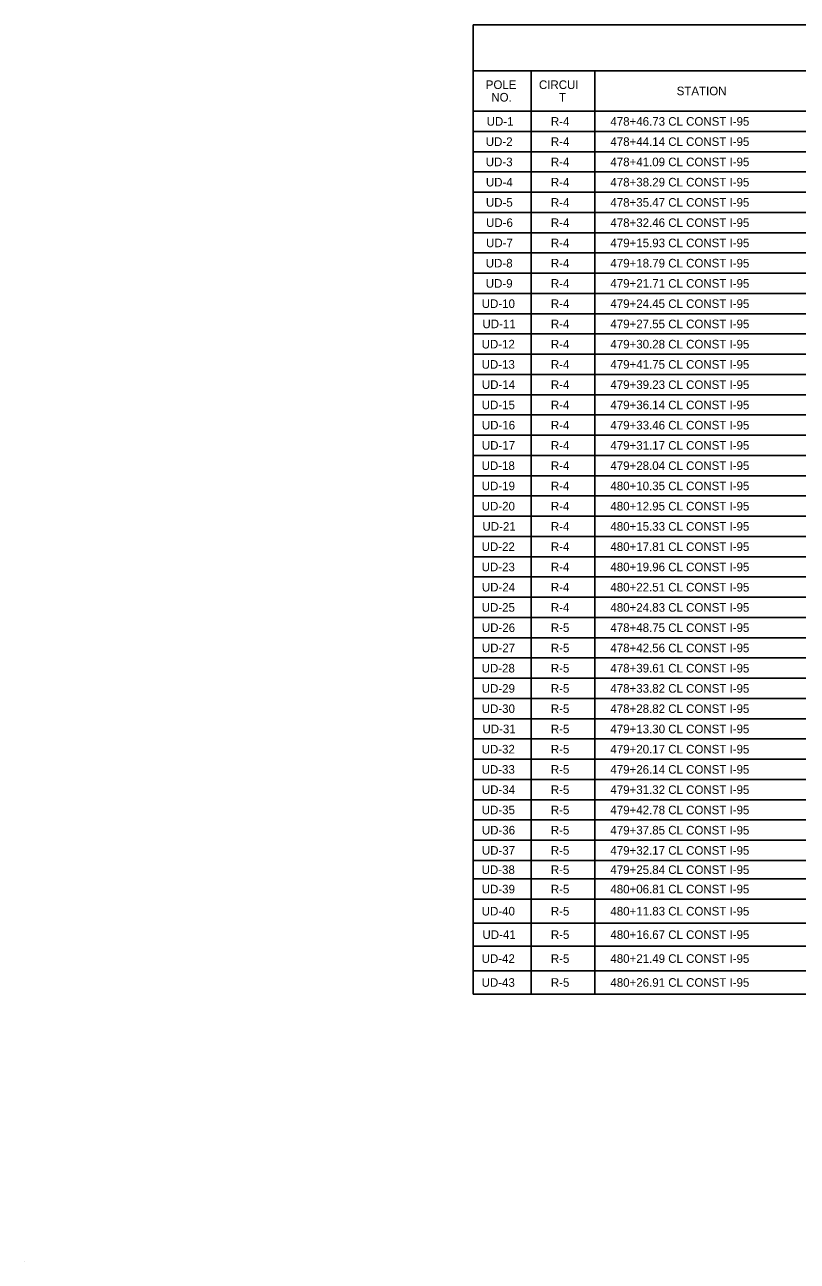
# Model space of a CAD drawing. Extents: x -816.7 to -800.9, y -2209.6 to -2187.8.
# Drawn here: x -816.67 to -810.38, y -2197.9 to -2187.82 of the extents above; entities that cross this region are included whole.
import ezdxf

# ---------------------------------------------------------------- set-up
doc = ezdxf.new("R2010")
doc.units = 0
for name, color, linetype in [('PlotBorder_dp', 7, 'Continuous'), ('SheetBorder_dp', 7, 'Continuous'), ('SheetLines_dp', 7, 'Continuous'), ('TextMinor', 7, 'Continuous'), ('TextShtNo', 7, 'Continuous')]:
    doc.layers.add(name, color=color, linetype=linetype)

msp = doc.modelspace()

# ---------------------------------------------------------------- linework, layer by layer
at = {"layer": 'PlotBorder_dp'}
for p, q in [((-812.544, -2188.198), (-812.544, -2195.721)), ((-812.544, -2188.198), (-812.544, -2195.721)), ((-812.026, -2188.198), (-812.026, -2195.721)), ((-812.026, -2188.198), (-812.026, -2195.721)), ((-813.016, -2188.528), (-803.889, -2188.528))]:
    msp.add_line(p, q, dxfattribs=at)
at = {"layer": 'SheetLines_dp'}
for p, q in [((-813.016, -2187.823), (-802.996, -2187.823)), ((-813.016, -2187.823), (-813.016, -2195.721)), ((-813.016, -2188.198), (-802.996, -2188.198)), ((-813.016, -2188.198), (-802.996, -2188.198)), ((-813.016, -2193.808), (-813.016, -2195.721)), ((-813.016, -2195.721), (-802.996, -2195.721))]:
    msp.add_line(p, q, dxfattribs=at)
at = {"layer": 'TextMinor'}
for p, q in [((-813.016, -2188.528), (-802.996, -2188.528)), ((-813.016, -2188.693), (-802.996, -2188.693)), ((-813.016, -2188.693), (-802.996, -2188.693)), ((-813.016, -2188.858), (-802.996, -2188.858)), ((-813.016, -2188.858), (-802.996, -2188.858)), ((-813.016, -2189.023), (-802.996, -2189.023)), ((-813.016, -2189.023), (-802.996, -2189.023)), ((-813.016, -2189.188), (-802.996, -2189.188)), ((-813.016, -2189.188), (-802.996, -2189.188)), ((-813.016, -2189.353), (-802.996, -2189.353)), ((-813.016, -2189.353), (-802.996, -2189.353)), ((-813.016, -2189.518), (-812.026, -2189.518)), ((-813.016, -2189.518), (-802.996, -2189.518)), ((-813.016, -2189.683), (-802.996, -2189.683)), ((-813.016, -2189.683), (-802.996, -2189.683)), ((-813.016, -2189.848), (-802.996, -2189.848)), ((-813.016, -2189.848), (-802.996, -2189.848)), ((-813.016, -2190.013), (-802.996, -2190.013)), ((-813.016, -2190.013), (-802.996, -2190.013)), ((-813.016, -2190.178), (-802.996, -2190.178)), ((-813.016, -2190.178), (-802.996, -2190.178)), ((-813.016, -2190.343), (-802.996, -2190.343)), ((-813.016, -2190.343), (-802.996, -2190.343)), ((-813.016, -2190.508), (-802.996, -2190.508)), ((-813.016, -2190.508), (-802.996, -2190.508)), ((-813.016, -2190.673), (-802.996, -2190.673)), ((-813.016, -2190.673), (-802.996, -2190.673)), ((-813.016, -2190.838), (-802.996, -2190.838)), ((-813.016, -2190.838), (-802.996, -2190.838)), ((-813.016, -2191.003), (-802.996, -2191.003)), ((-813.016, -2191.003), (-802.996, -2191.003)), ((-813.016, -2191.168), (-802.996, -2191.168)), ((-813.016, -2191.168), (-802.996, -2191.168)), ((-813.016, -2191.333), (-802.996, -2191.333)), ((-813.016, -2191.333), (-802.996, -2191.333)), ((-813.016, -2191.498), (-802.996, -2191.498)), ((-813.016, -2191.498), (-802.996, -2191.498)), ((-813.016, -2191.663), (-802.996, -2191.663)), ((-813.016, -2191.663), (-802.996, -2191.663)), ((-813.016, -2191.828), (-802.996, -2191.828)), ((-813.016, -2191.828), (-802.996, -2191.828)), ((-813.016, -2191.993), (-802.996, -2191.993)), ((-813.016, -2191.993), (-802.996, -2191.993)), ((-813.016, -2192.158), (-802.996, -2192.158)), ((-813.016, -2192.158), (-802.996, -2192.158)), ((-813.016, -2192.323), (-802.996, -2192.323)), ((-813.016, -2192.323), (-802.996, -2192.323)), ((-813.016, -2192.488), (-802.996, -2192.488)), ((-813.016, -2192.488), (-802.996, -2192.488)), ((-813.016, -2192.653), (-802.996, -2192.653)), ((-813.016, -2192.653), (-802.996, -2192.653)), ((-813.016, -2192.818), (-802.996, -2192.818)), ((-813.016, -2192.818), (-802.996, -2192.818)), ((-813.016, -2192.983), (-802.996, -2192.983)), ((-813.016, -2192.983), (-802.996, -2192.983)), ((-813.016, -2193.148), (-802.996, -2193.148)), ((-813.016, -2193.148), (-802.996, -2193.148)), ((-813.016, -2193.313), (-802.996, -2193.313)), ((-813.016, -2193.313), (-802.996, -2193.313)), ((-813.016, -2193.478), (-802.996, -2193.478)), ((-813.016, -2193.478), (-802.996, -2193.478)), ((-813.016, -2193.643), (-802.996, -2193.643)), ((-813.016, -2193.643), (-802.996, -2193.643)), ((-813.016, -2193.808), (-802.996, -2193.808)), ((-813.016, -2193.808), (-802.996, -2193.808)), ((-813.016, -2193.973), (-802.996, -2193.973)), ((-813.016, -2193.973), (-802.996, -2193.973)), ((-813.016, -2194.138), (-802.996, -2194.138)), ((-813.016, -2194.138), (-802.996, -2194.138)), ((-813.016, -2194.303), (-802.996, -2194.303)), ((-813.016, -2194.303), (-802.996, -2194.303)), ((-813.016, -2194.468), (-802.996, -2194.468)), ((-813.016, -2194.468), (-802.996, -2194.468)), ((-813.016, -2194.633), (-802.996, -2194.633)), ((-813.016, -2194.633), (-802.996, -2194.633)), ((-813.016, -2194.783), (-802.996, -2194.783)), ((-813.016, -2194.783), (-802.996, -2194.783)), ((-813.016, -2194.948), (-802.996, -2194.948)), ((-813.016, -2194.948), (-802.996, -2194.948)), ((-813.016, -2195.143), (-802.996, -2195.143)), ((-813.016, -2195.143), (-802.996, -2195.143)), ((-813.016, -2195.331), (-802.996, -2195.331)), ((-813.016, -2195.331), (-802.996, -2195.331)), ((-813.016, -2195.533), (-802.996, -2195.533)), ((-813.016, -2195.533), (-802.996, -2195.533))]:
    msp.add_line(p, q, dxfattribs=at)
at = {"layer": 'TextShtNo'}
msp.add_line((-816.669, -2197.899), (-816.669, -2197.899), dxfattribs=at)

# ---------------------------------------------------------------- texts
at = {"layer": 'SheetBorder_dp'}
for s, p in [('POLE', (-812.913, -2188.347)), ('CIRCUI', (-812.48, -2188.347)), ('STATION', (-811.358, -2188.398)), ('NO.', (-812.868, -2188.449)), ('T', (-812.317, -2188.449)), ('UD-1', (-812.906, -2188.646)), ('R-4', (-812.383, -2188.646)), ('478+46.73 CL CONST I-95', (-811.898, -2188.646)), ('UD-2', (-812.913, -2188.811)), ('R-4', (-812.383, -2188.811)), ('478+44.14 CL CONST I-95', (-811.898, -2188.811)), ('UD-3', (-812.913, -2188.976)), ('R-4', (-812.383, -2188.976)), ('478+41.09 CL CONST I-95', (-811.898, -2188.976)), ('UD-4', (-812.912, -2189.141)), ('R-4', (-812.383, -2189.141)), ('478+38.29 CL CONST I-95', (-811.898, -2189.141)), ('UD-5', (-812.912, -2189.306)), ('R-4', (-812.383, -2189.306)), ('478+35.47 CL CONST I-95', (-811.898, -2189.306)), ('UD-6', (-812.911, -2189.471)), ('R-4', (-812.383, -2189.471)), ('478+32.46 CL CONST I-95', (-811.898, -2189.471)), ('UD-7', (-812.911, -2189.636)), ('R-4', (-812.383, -2189.636)), ('479+15.93 CL CONST I-95', (-811.898, -2189.636)), ('UD-8', (-812.913, -2189.801)), ('R-4', (-812.383, -2189.801)), ('479+18.79 CL CONST I-95', (-811.898, -2189.801)), ('UD-9', (-812.913, -2189.966)), ('R-4', (-812.383, -2189.966)), ('479+21.71 CL CONST I-95', (-811.898, -2189.966)), ('UD-10', (-812.946, -2190.131)), ('R-4', (-812.383, -2190.131)), ('479+24.45 CL CONST I-95', (-811.898, -2190.131)), ('UD-11', (-812.94, -2190.296)), ('R-4', (-812.383, -2190.296)), ('479+27.55 CL CONST I-95', (-811.898, -2190.296)), ('UD-12', (-812.947, -2190.461)), ('R-4', (-812.383, -2190.461)), ('479+30.28 CL CONST I-95', (-811.898, -2190.461)), ('UD-13', (-812.947, -2190.626)), ('R-4', (-812.383, -2190.626)), ('479+41.75 CL CONST I-95', (-811.898, -2190.626)), ('UD-14', (-812.945, -2190.791)), ('R-4', (-812.383, -2190.791)), ('479+39.23 CL CONST I-95', (-811.898, -2190.791)), ('UD-15', (-812.946, -2190.956)), ('R-4', (-812.383, -2190.956)), ('479+36.14 CL CONST I-95', (-811.898, -2190.956)), ('UD-16', (-812.945, -2191.121)), ('R-4', (-812.383, -2191.121)), ('479+33.46 CL CONST I-95', (-811.898, -2191.121)), ('UD-17', (-812.945, -2191.286)), ('R-4', (-812.383, -2191.286)), ('479+31.17 CL CONST I-95', (-811.898, -2191.286)), ('UD-18', (-812.947, -2191.451)), ('R-4', (-812.383, -2191.451)), ('479+28.04 CL CONST I-95', (-811.898, -2191.451)), ('UD-19', (-812.946, -2191.616)), ('R-4', (-812.383, -2191.616)), ('480+10.35 CL CONST I-95', (-811.898, -2191.616)), ('UD-20', (-812.946, -2191.781)), ('R-4', (-812.383, -2191.781)), ('480+12.95 CL CONST I-95', (-811.898, -2191.781)), ('UD-21', (-812.94, -2191.946)), ('R-4', (-812.383, -2191.946)), ('480+15.33 CL CONST I-95', (-811.898, -2191.946)), ('UD-22', (-812.947, -2192.111)), ('R-4', (-812.383, -2192.111)), ('480+17.81 CL CONST I-95', (-811.898, -2192.111)), ('UD-23', (-812.947, -2192.276)), ('R-4', (-812.383, -2192.276)), ('480+19.96 CL CONST I-95', (-811.898, -2192.276)), ('UD-24', (-812.945, -2192.441)), ('R-4', (-812.383, -2192.441)), ('480+22.51 CL CONST I-95', (-811.898, -2192.441)), ('UD-25', (-812.946, -2192.606)), ('R-4', (-812.383, -2192.606)), ('480+24.83 CL CONST I-95', (-811.898, -2192.606)), ('UD-26', (-812.945, -2192.771)), ('R-5', (-812.383, -2192.771)), ('478+48.75 CL CONST I-95', (-811.898, -2192.771)), ('UD-27', (-812.945, -2192.936)), ('R-5', (-812.383, -2192.936)), ('478+42.56 CL CONST I-95', (-811.898, -2192.936)), ('UD-28', (-812.947, -2193.101)), ('R-5', (-812.383, -2193.101)), ('478+39.61 CL CONST I-95', (-811.898, -2193.101)), ('UD-29', (-812.946, -2193.266)), ('R-5', (-812.383, -2193.266)), ('478+33.82 CL CONST I-95', (-811.898, -2193.266)), ('UD-30', (-812.946, -2193.431)), ('R-5', (-812.383, -2193.431)), ('478+28.82 CL CONST I-95', (-811.898, -2193.431)), ('UD-31', (-812.94, -2193.596)), ('R-5', (-812.383, -2193.596)), ('479+13.30 CL CONST I-95', (-811.898, -2193.596)), ('UD-32', (-812.947, -2193.761)), ('R-5', (-812.383, -2193.761)), ('479+20.17 CL CONST I-95', (-811.898, -2193.761)), ('UD-33', (-812.947, -2193.926)), ('R-5', (-812.383, -2193.926)), ('479+26.14 CL CONST I-95', (-811.898, -2193.926)), ('UD-34', (-812.945, -2194.091)), ('R-5', (-812.383, -2194.091)), ('479+31.32 CL CONST I-95', (-811.898, -2194.091)), ('UD-35', (-812.946, -2194.256)), ('R-5', (-812.383, -2194.256)), ('479+42.78 CL CONST I-95', (-811.898, -2194.256)), ('UD-36', (-812.945, -2194.421)), ('R-5', (-812.383, -2194.421)), ('479+37.85 CL CONST I-95', (-811.898, -2194.421)), ('UD-37', (-812.945, -2194.586)), ('R-5', (-812.383, -2194.586)), ('479+32.17 CL CONST I-95', (-811.898, -2194.586)), ('UD-38', (-812.947, -2194.743)), ('R-5', (-812.383, -2194.743)), ('479+25.84 CL CONST I-95', (-811.898, -2194.743)), ('UD-39', (-812.946, -2194.901)), ('R-5', (-812.383, -2194.901)), ('480+06.81 CL CONST I-95', (-811.898, -2194.901)), ('UD-40', (-812.946, -2195.081)), ('R-5', (-812.383, -2195.081)), ('480+11.83 CL CONST I-95', (-811.898, -2195.081)), ('UD-41', (-812.94, -2195.272)), ('R-5', (-812.383, -2195.272)), ('480+16.67 CL CONST I-95', (-811.898, -2195.272)), ('UD-42', (-812.947, -2195.467)), ('R-5', (-812.383, -2195.467)), ('480+21.49 CL CONST I-95', (-811.898, -2195.467)), ('UD-43', (-812.947, -2195.662)), ('R-5', (-812.383, -2195.662)), ('480+26.91 CL CONST I-95', (-811.898, -2195.662))]:
    msp.add_text(s, height=0.07, dxfattribs=at).set_placement(p)

doc.saveas('drawing.dxf')
